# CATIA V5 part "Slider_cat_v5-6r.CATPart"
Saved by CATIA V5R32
Part number: Slider
Bounding box of the stored display mesh (mm): x -10 to 10, y -69.282 to 69.282, z -70 to 10
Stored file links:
  D:\PROJECTS\Project 2022\CATIA V5 6R 2022\Resources\Tutorial Files\c16_catia_v5_6r2022_tut\Slide Curve\Slider_cat_v5-6r.CATPart
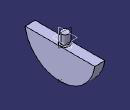
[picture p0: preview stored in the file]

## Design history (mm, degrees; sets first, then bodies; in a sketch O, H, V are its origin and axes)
Body1 (main body)
  Sketch1 on yz-plane, origin (0, 0, 0), H (0, 1, 0), V (0, 0, 1)
    arc A1 centre (0, 0) radius 70 from (-69.282, -10) to (69.282, -10) ccw
    point P1 (0, 0)
    point P2 (-69.282, -10)
    point P3 (69.282, -10)
    point P4 (0, 0)
    point P5 (-69.282, -10)
    line L1 (-69.282, -10) -> (69.282, -10)
    point P6 (69.282, -10)
    point P7 (-69.282, -10)
    reference intersected line E1 through (0, 0) direction (-1, 0) from xy-plane
    reference intersected line E3 through (0, 0) direction (0, 1) from zx-plane
    radius A1 = 70
    distance L1 P1 = 10
    coincidence: P1 V, P4 V, P6 P3, P7 A1, P2 P7, E3 P1, P2 L1, P3 L1, H P4, P2 P5, P1 H
    horizontal: L1 H, E1 H
    vertical: E3 V
    perpendicularity: E3 L1
  Pad1: profile Sketch1, direction (1, 0, 0), length 10, mirrored extent
  Point1: type OnCurve, Support edge [face of Pad1 from Sketch1.A1 | end face of Pad1], Ratio 0.5
  Sketch2 on face of Pad1 from Sketch1.L1, origin (0, 0, -10), H (1, 0, 0), V (0, 1, 0)
    circle A1 centre (0, 0) radius 7.5
    point P1 (0, 0)
    reference projected line E1 (10, 69.282) -> (10, -69.282) from edge [face of Pad1 from Sketch1.L1 | end face of Pad1]
    radius A1 = 7.5
    distance P1 E1 = 10
    coincidence: P1 H
  Pad2: profile Sketch2, direction (0, 0, 1), length 20
  Fillet1: radius 2, on edge [face of Pad1 from Sketch1.L1 | face of Pad2 from Sketch2.A1]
